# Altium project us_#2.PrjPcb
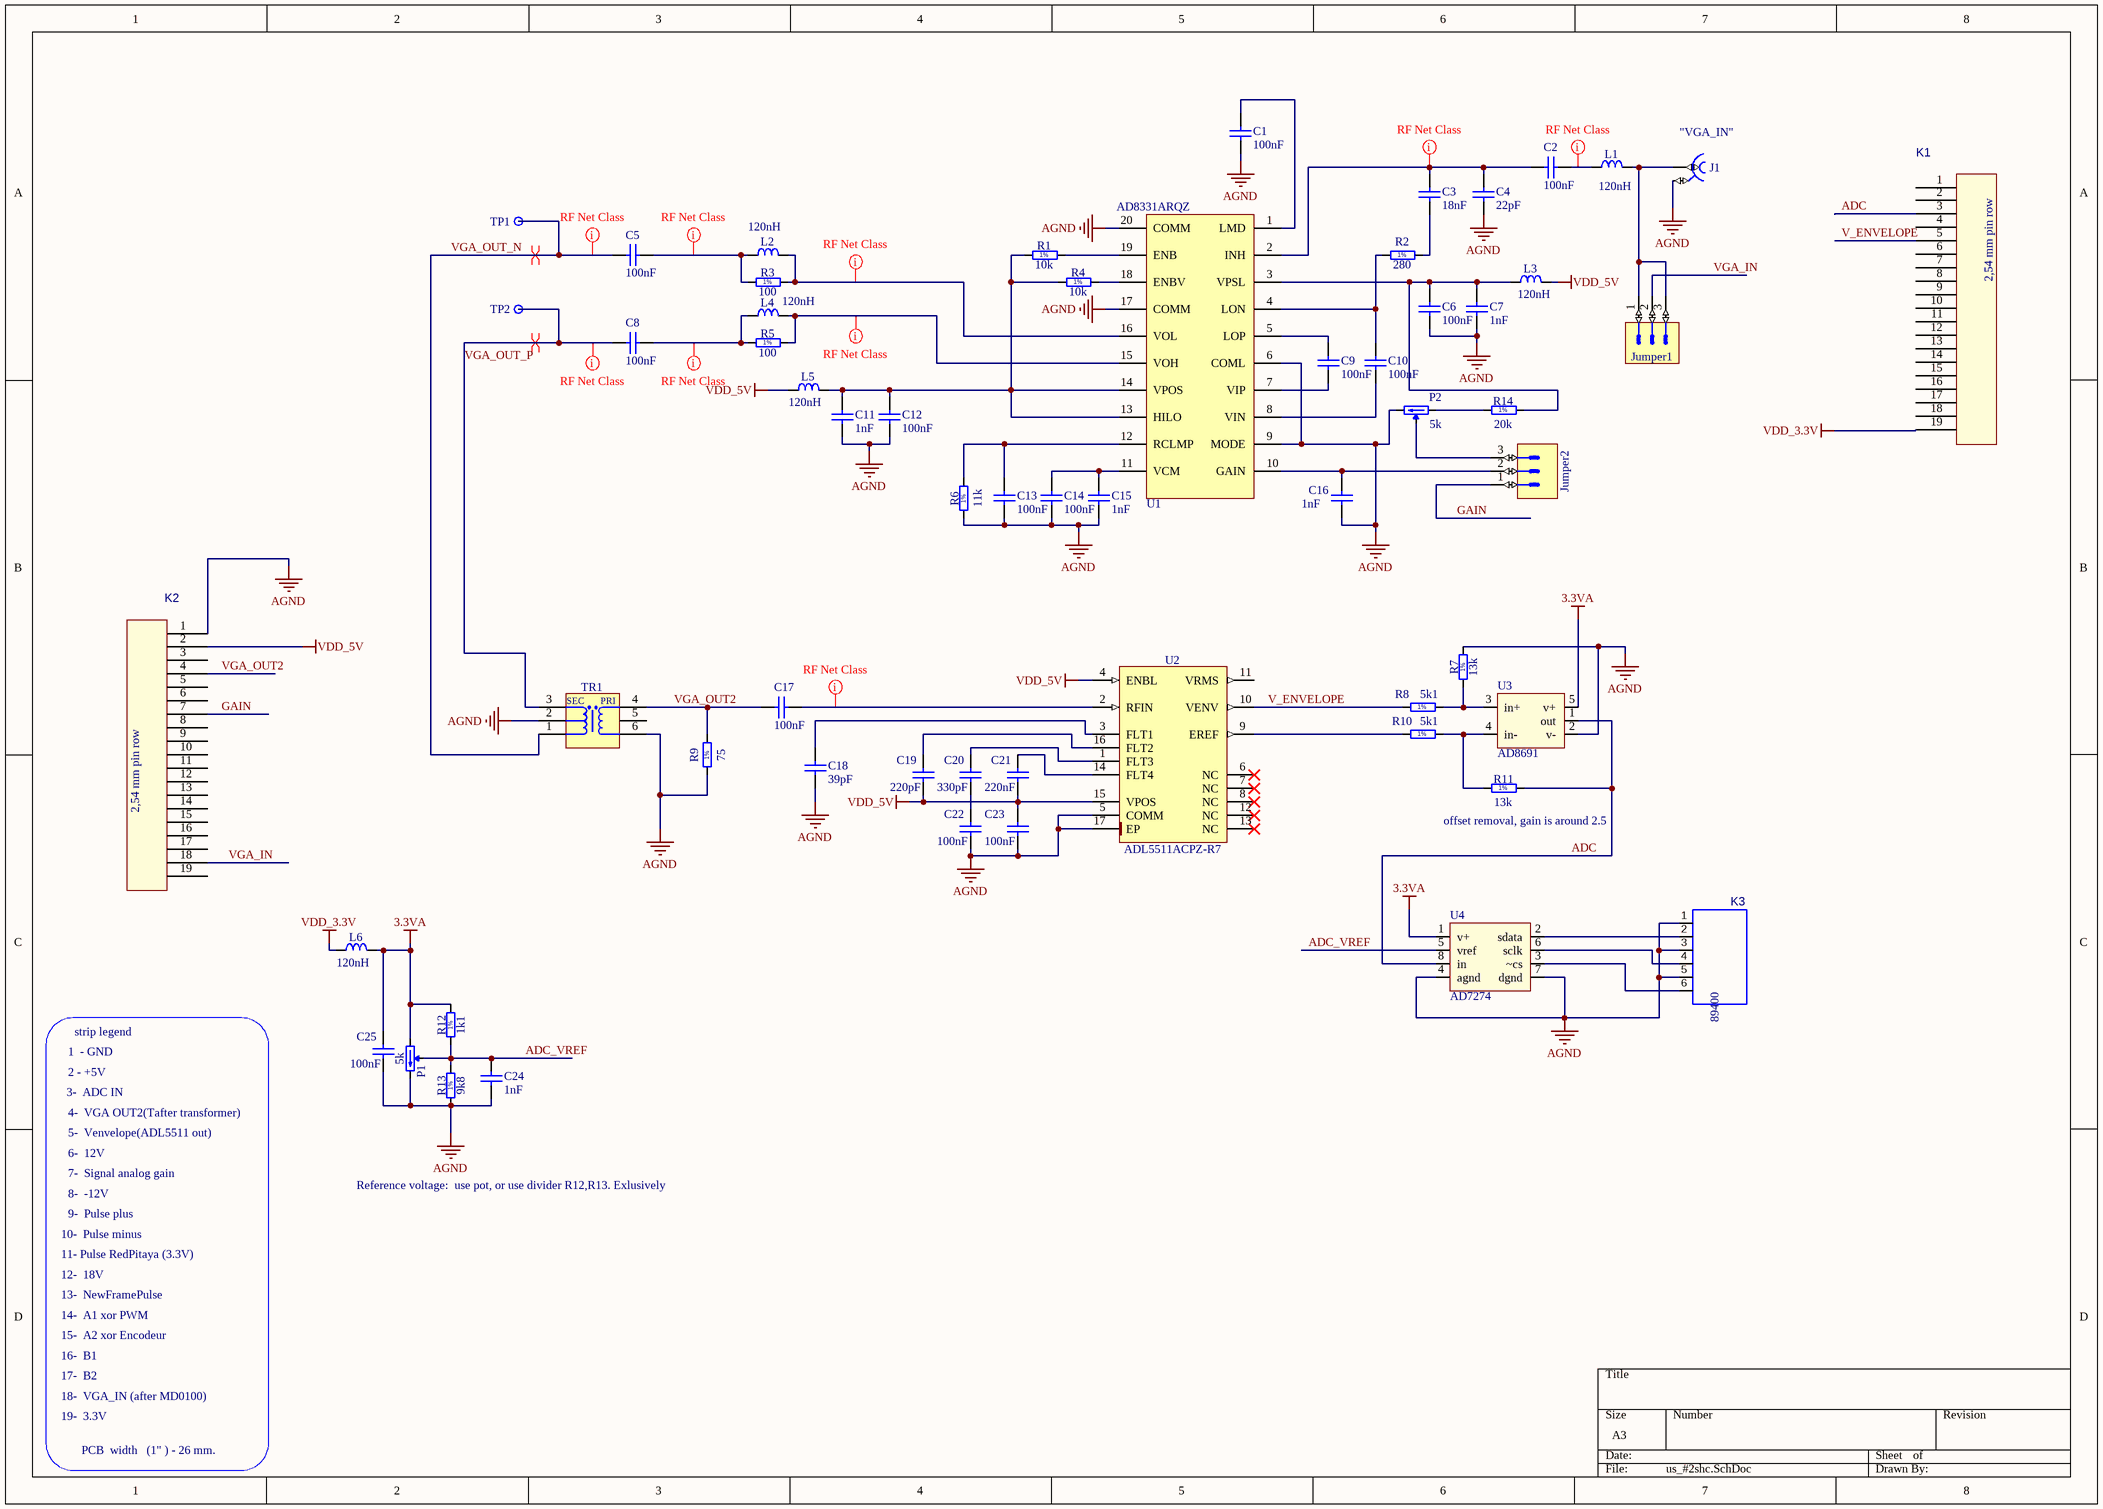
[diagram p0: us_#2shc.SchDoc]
1 sheet, 60 parts. Net scope: global (net labels, ports and power ports of the same name join across sheets).
Board files: us_#2.PcbDoc, PCB1_logo.PcbDoc

## Sheet us_#2shc.SchDoc
size A3

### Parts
C1  value 100nF  [SM0603 _3D_cap]  (hidden comment: cap0603)
C2  value 100nF  [SM0603 _3D_cap]  (hidden comment: cap0603)
C3  value 18nF  [SM0603 _3D_cap]  (hidden comment: cap0603)
C4  value 22pF  [SM0603 _3D_cap]  (hidden comment: cap0603)
C5  value 100nF  [SM0603 _3D_cap]  (hidden comment: cap0603)
C6  value 100nF  [SM0603 _3D_cap]  (hidden comment: cap0603)
C7  value 1nF  [SM0603 _3D_cap]  (hidden comment: cap0603)
C8  value 100nF  [SM0603 _3D_cap]  (hidden comment: cap0603)
C9  value 100nF  [SM0603 _3D_cap]  (hidden comment: cap0603)
C10  value 100nF  [SM0603 _3D_cap]  (hidden comment: cap0603)
C11  value 1nF  [SM0603 _3D_cap]  (hidden comment: cap0603)
C12  value 100nF  [SM0603 _3D_cap]  (hidden comment: cap0603)
C13  value 100nF  [SM0603 _3D_cap]  (hidden comment: cap0603)
C14  value 100nF  [SM0603 _3D_cap]  (hidden comment: cap0603)
C15  value 1nF  [SM0603 _3D_cap]  (hidden comment: cap0603)
C16  value 1nF  [SM0603 _3D_cap]  (hidden comment: cap0603)
C17  value 100nF  [SM0603 _3D_cap]  (hidden comment: cap0603)
C18  value 39pF  [SM0603 _3D_cap]  (hidden comment: cap0603)
C19  value 220pF  [SM0603 _3D_cap]  (hidden comment: cap0603)
C20  value 330pF  [SM0603 _3D_cap]  (hidden comment: cap0603)
C21  value 220nF  [SM0603 _3D_cap]  (hidden comment: cap0603)
C22  value 100nF  [SM0603 _3D_cap]  (hidden comment: cap0603)
C23  value 100nF  [SM0603 _3D_cap]  (hidden comment: cap0603)
C24  value 1nF  [SM0603 _3D_cap]  (hidden comment: cap0603)
C25  value 100nF  [SM0603 _3D_cap]  (hidden comment: cap0603)
J1  SMA  [AMPHENOL_132357-11]  (value not drawn)
Jumper1  (no value)  [SULLINS_GRPB031VWVN]
Jumper2  (no value)  [SULLINS_GRPB031VWVN]
K1  PLS_2.54mm-19  [PLS_2.54mm-19]  (value not drawn)
K2  PLS_2.54mm-19  [PLS_2.54mm-19]  (value not drawn)
K3  Molex_89400_061  [Molex_89400-061]  (value not drawn)
L1  75R@100MHz  [SM_0805_INDUCTANCE _3D]  (value not drawn)
L2  75R@100MHz  [SM_0805_INDUCTANCE _3D]  (value not drawn)
L3  75R@100MHz  [SM_0805_INDUCTANCE _3D]  (value not drawn)
L4  75R@100MHz  [SM_0805_INDUCTANCE _3D]  (value not drawn)
L5  75R@100MHz  [SM_0805_INDUCTANCE _3D]  (value not drawn)
L6  75R@100MHz  [SM_0805_INDUCTANCE _3D]  (value not drawn)
P1  5k  [TRIM_BOURNS_3223W]
P2  5k  [TRIM_BOURNS_3223W]
R1  10k  [SM0603_3D_res]
R2  280  [SM0603_3D_res]
R3  100  [SM0603_3D_res]
R4  10k  [SM0603_3D_res]
R5  100  [SM0603_3D_res]
R6  11k  [SM0603_3D_res]
R7  13k  [SM0603_3D_res]
R8  5k1  [SM0603_3D_res]
R9  75  [SM0603_3D_res]
R10  5k1  [SM0603_3D_res]
R11  13k  [SM0603_3D_res]
R12  1k1  [SM0603_3D_res]
R13  9k8  [SM0603_3D_res]
R14  20k  [SM0603_3D_res]
TP1  Test Point  [NICOMATIC_C12000B]  (value not drawn)
TP2  Test Point  [NICOMATIC_C12000B]  (value not drawn)
TR1  1:1  [XFMR_MINI-CIRCUITS_KK81]  (value not drawn)
U1  AD8331ARQZ  [SOP64P600X175-20N]
U2  ADL5511ACPZ-R7  [QFN50P300X300X80-17N-S175]
U3  AD8691  [TSOT-5(RT-5)]
U4  AD7274  [RM-8]

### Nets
3.3VA: C25.2 L6.2 P1.1(CCW) R12.2 U3.5(v+) U4.1(v+)
AGND: C1.1 C4.1 C6.1 C7.1 C11.1 C12.1 C13.1 C14.1 C15.1 C16.1 C18.1 C22.1 C23.1 C24.1 C25.1 J1.2 K2.1 K3.1 K3.3 K3.5 P1.3(CW) P2.3(CW) R6.1 R7.2 R9.1 R13.1 TR1.2(NC) TR1.6(S) U1.6(COML) U1.9(MODE) U1.17(COMM) U1.20(COMM) U2.5(COMM) U2.17(EP) U3.2(v-) U4.4(agnd) U4.7(dgnd)
VDD_3.3V: K1.19 L6.1
VDD_5V: C19.1 C21.1 C23.2 K2.2 L3.2 L5.1 U2.4(ENBL) U2.15(VPOS)
ADC: K1.3 R11.2 U3.1(out) U4.8(in)
ADC_VREF: C24.2 P1.2(W) R12.1 R13.2 U4.5(vref)
GAIN: Jumper2.1 K2.7
V_ENVELOPE: K1.5 R8.1 U2.10(VENV)
VGA_IN: Jumper1.2 K2.18
VGA_OUT2: C17.1 K2.4 R9.2 TR1.4(SDOT)
VGA_OUT_N: C5.1 TP1.1 TR1.1(P)
VGA_OUT_P: C8.2 TP2.1 TR1.3(PDOT)
NetC1_2: C1.2 U1.1(LMD)
NetC2_1: C2.1 C3.2 C4.2 U1.2(INH)
NetC2_2: C2.2 L1.1
NetC3_1: C3.1 R2.2
NetC5_2: C5.2 L2.1 R3.1
NetC6_2: C6.2 C7.2 L3.1 R14.2 U1.3(VPSL)
NetC8_1: C8.1 L4.1 R5.1
NetC9_1: C9.1 U1.7(VIP)
NetC9_2: C9.2 U1.5(LOP)
NetC10_1: C10.1 U1.8(VIN)
NetC10_2: C10.2 R2.1 U1.4(LON)
NetC11_2: C11.2 C12.2 L5.2 R1.1 R4.1 U1.13(HILO) U1.14(VPOS)
NetC13_2: C13.2 R6.2 U1.12(RCLMP)
NetC14_2: C14.2 C15.2 U1.11(VCM)
NetC16_2: C16.2 Jumper2.2 U1.10(GAIN)
NetC17_2: C17.2 U2.2(RFIN)
NetC18_2: C18.2 U2.3(FLT1)
NetC19_2: C19.2 U2.16(FLT2)
NetC20_1: C20.1 C22.2
NetC20_2: C20.2 U2.1(FLT3)
NetC21_2: C21.2 U2.14(FLT4)
NetJ1_1: J1.1 Jumper1.1 Jumper1.3 L1.2
NetJumper2_3: Jumper2.3 P2.2(W)
NetK3_2: K3.2 U4.2(sdata)
NetK3_4: K3.4 U4.6(sclk)
NetK3_6: K3.6 U4.3(~cs)
NetL2_2: L2.2 R3.2 U1.16(VOL)
NetL4_2: L4.2 R5.2 U1.15(VOH)
NetP2_1: P2.1(CCW) R14.1
NetR1_2: R1.2 U1.19(ENB)
NetR4_2: R4.2 U1.18(ENBV)
NetR7_1: R7.1 R8.2 U3.3(in+)
NetR10_1: R10.1 U2.9(EREF)
NetR10_2: R10.2 R11.1 U3.4(in-)

Not connected (* = marked no-connect by the designer): K1 1 2 4 6 7 8 9 10 11 12 13 14 15 16 17 18; K2 3 5 6 8 9 10 11 12 13 14 15 16 17 19; TR1 5(NC); U2 6(NC)* 7(NC)* 8(NC)* 11(VRMS) 12(NC)* 13(NC)*

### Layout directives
net class RF: NetC2_1, NetC2_2, NetC5_2, NetC8_1, NetC17_2, NetL2_2, NetL4_2, VGA_OUT_N, VGA_OUT_P
differential pair: VGA_OUT_N, VGA_OUT_P

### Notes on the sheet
- (near J1) "VGA_IN"
- (near L2) 120nH
- (near L1) 120nH
- 120nH
- (near L3) 120nH
- (near L5) 120nH
- (near R11) offset removal, gain is around 2.5
- (near L6) 120nH
- 1  - GND
- strip legend
- 3-  ADC IN
- 2 - +5V
- 4-  VGA OUT2(Tafter transformer)
- 5-  Venvelope(ADL5511 out)
- 6-  12V
- 7-  Signal analog gain
- Reference voltage:  use pot, or use divider R12,R13. Exlusively
- 10-  Pulse minus
- 11- Pulse RedPitaya (3.3V)
- 8-  -12V
- 9-  Pulse plus
- 12-  18V
- 13-  NewFramePulse
- 14-  A1 xor PWM
- 15-  A2 xor Encodeur
- 16-  B1
- 17-  B2
- 18-  VGA_IN (after MD0100)
- 19-  3.3V
- PCB  width   (1" ) - 26 mm.

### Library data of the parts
C1-C25 = cap0603: Capacitor  0603 inch
J1 = Coax_1Female_1Shield: Part Description: SMA End Launch Jack for 1.58mm PCB, 50 Ohm, Flat Tab Contact; Manufacturer: AMPHENOL; Manufacturer Part Number: 132357-11
Jumper1 Jumper2 = SULLINS_GRPB031VWVN: Connector 3 Male; Part Description: 3 Contact 0.5" Pitch Single-In-Line Vertical Header; Table: Miscellaneous
K3 = Molex_89400_061: 6 pin vertical 2mm
L1-L6 = Ind_Chip: chip inductance; Part Number: IND0805_MURATA_BLM21BB750SN1D; Part Description: SMD EMIFIL Suppression Chip Ferrite Bead; Manufacturer: MURATA; Manufacturer Part Number: BLM21BB750SN1D; Power: 700mA; Resistance: 0.16R; Tolerance: ±25%; Table: Inductors SMD
P1 P2 = Trimming Potentiometer: Part Number: TRIM_11T_5K_BOURNS_3223W-1-502E; Part Description: 11 Turns SMD Trimpot® Trimming Potentiometer (Top Adjust); Manufacturer: BOURNS; Manufacturer Part Number: 3223W-1-502E; Power: 0.125W; TC: ±100ppm/°C; Tolerance: ±20%; Table: Potentiometers SMD
R1-R14 = Res_0603_1%_EU: Part Number: R1206_4K7_1%_0.25W_100PPM; Part Description: General Purpose Thick Film Chip Resistor; Manufacturer: GENERIC; Manufacturer1 Part Number: NRC12F4701TRF; Value: 4k7; Power: 0.25W; TC: ±100ppm/°C; Tolerance: ±1%; Table: Resistors SMD
TP1 TP2 = NICOMATIC_C12000B: Part Description: SMD Test Point; Table: Miscellaneous
TR1 = XFMR_MINI-CIRCUITS_T1-6T-KK81: 50 Ohm 0.015 To 300MHz RF Transformers; Part Description: 50 Ohms 0.015 To 300MHz RF Transformers
U1 = AD8331ARQZ: Part Description: Ultralow Noise VGAs with Preamplifier and Programmable RIN; Manufacturer: Analog Devices; Table: Analog & Interface
U2 = ADL5511ACPZ-R7: DC to 6 GHz Envelope and TruPwr RMS Detector; Manufacturer: ANALOG DEVICES; Table: Analog & Interface
U3 = OpAmp_TSOT5
U4 = AD7274: adc serial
